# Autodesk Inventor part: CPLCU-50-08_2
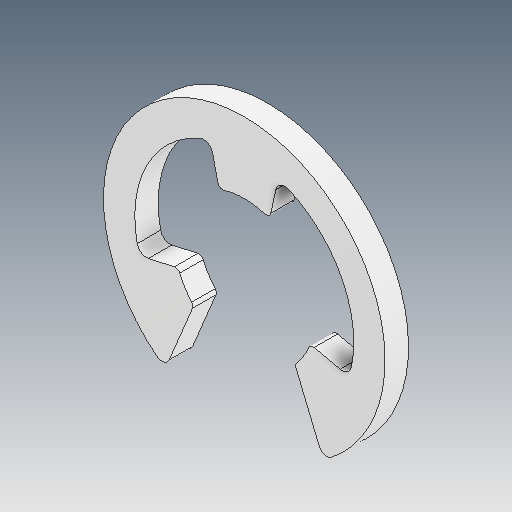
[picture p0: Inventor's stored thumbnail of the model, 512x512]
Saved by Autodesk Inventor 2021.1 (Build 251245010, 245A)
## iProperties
Created: 2021-06
Part Number: CPLCU-50-08_2
Material: Ogólny
Document SubType Name: Modeling
Designer: user
Density: 1 g/cm^3
Appearance: Domyślna
Author: user
Revision Number: ÈÎºÎ
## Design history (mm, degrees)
feature "ÊäÈë1"
node "Bryła1"
